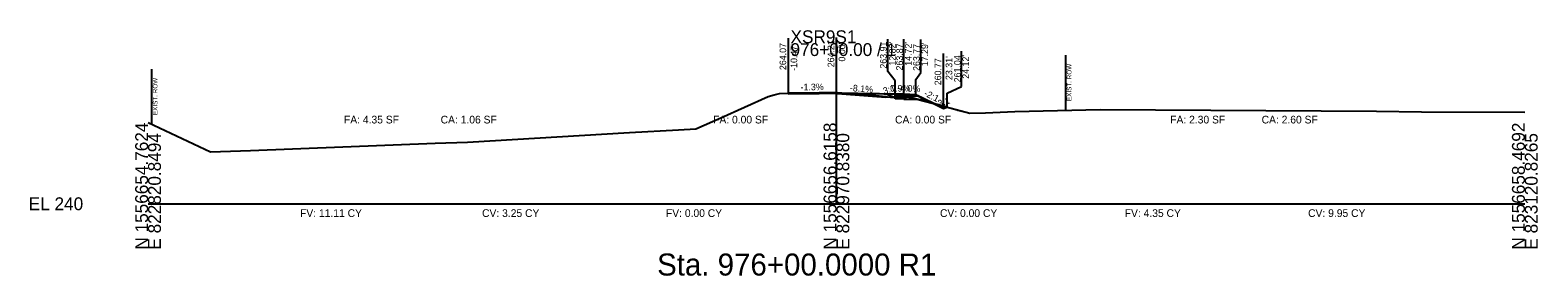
# Model space of a CAD drawing. Extents: x -26 to 823017, y -16 to 1558356.
# Drawn here: x 1974.3 to 2302.8, y 7484.3 to 7537.8 of the extents above; entities that cross this region are included whole.
import ezdxf

# ---------------------------------------------------------------- set-up
doc = ezdxf.new("R2010")
doc.units = 0
for name, color, linetype in [('ASPHALT_19MM1', 7, 'Continuous'), ('CONST_DCH', 7, 'Continuous'), ('CONST_LV3', 7, 'Continuous'), ('Draft_XS_Grid', 7, 'Continuous'), ('Draft_XS_Text', 7, 'Continuous'), ('DTM_CORRIDOR', 7, 'Continuous'), ('DTM_P_FINISHED_GRADE2', 7, 'Continuous'), ('DTM_X_GROUND', 7, 'Continuous'), ('SLOPE_STAKES_FILL', 7, 'Continuous'), ('X_TRANS_EOP', 7, 'Continuous'), ('XS_CELL', 7, 'Continuous'), ('XS_P_ASPHALT', 7, 'Continuous'), ('XS_P_DR_GRAVEL', 7, 'Continuous'), ('XS_P_GROUND', 7, 'Continuous'), ('XS_P_NULL_POINT', 7, 'Continuous'), ('XS_P_SHOULDER', 7, 'Continuous'), ('XS_P_SUBGRADE_GRANULAR', 7, 'Continuous'), ('XS_P_SUBGRADE_LEVELING', 7, 'Continuous'), ('XS_P_SUBGRADE_MILLING', 7, 'Continuous'), ('XS_P_SUBGRADE_UNDERCUT', 7, 'Continuous'), ('XS_P_TX_CLEARZONE', 7, 'Continuous'), ('XS_P_TX_FS_BS', 7, 'Continuous'), ('XS_SHEET_EW_TX_AREA', 7, 'Continuous'), ('XS_SHEET_EW_TX_VOLUME', 7, 'Continuous'), ('XS_X_ROW', 7, 'Continuous')]:
    doc.layers.add(name, color=color, linetype=linetype)

msp = doc.modelspace()

# ---------------------------------------------------------------- linework, layer by layer
at = {"layer": 'ASPHALT_19MM1'}
msp.add_lwpolyline([(2162.82, 7523.75), (2162.82, 7523.54), (2164.72, 7523.5), (2164.72, 7523.7), (2162.82, 7523.75)], dxfattribs=at)
at = {"layer": 'CONST_LV3'}
for points in [[(2000, 7517.72), (2013.59, 7511.28), (2022.29, 7511.63), (2062.59, 7513.21), (2069.61, 7513.42), (2104.93, 7515.51), (2115.58, 7516.11), (2119.34, 7516.33), (2124.8, 7518.75), (2135.15, 7523.36), (2136.41, 7523.72), (2137.57, 7524.05), (2139.53, 7524.07), (2139.53, 7524.07)], [(2150, 7524.21), (2164, 7523.93)], [(2160.77, 7523.33), (2160.77, 7523.33), (2162.82, 7523.16), (2163.01, 7523.16), (2164.72, 7523.12), (2166.98, 7523.69), (2167.29, 7523.77), (2170.58, 7522.13), (2171.2, 7521.82), (2173.88, 7521.1), (2176.33, 7520.45), (2176.43, 7520.42), (2179.05, 7519.73), (2182.47, 7519.85), (2188.84, 7520.08), (2207.48, 7520.58), (2267.71, 7520.15), (2277.51, 7520.07), (2300, 7519.96)], [(2162.77, 7523.98), (2164, 7523.93), (2164, 7523.93)]]:
    msp.add_lwpolyline(points, dxfattribs=at)
at = {"layer": 'DTM_P_FINISHED_GRADE2'}
msp.add_lwpolyline([(2139.53, 7524.07), (2150, 7524.21), (2160.77, 7523.96)], dxfattribs=at)
at = {"layer": 'DTM_X_GROUND'}
for points in [[(2000, 7517.72), (2013.59, 7511.28), (2022.29, 7511.63), (2062.59, 7513.21), (2069.61, 7513.42), (2104.93, 7515.51), (2115.58, 7516.11), (2119.34, 7516.33), (2124.8, 7518.75), (2135.15, 7523.36), (2136.41, 7523.72), (2137.57, 7524.05), (2146.22, 7524.16), (2150.21, 7524.21), (2157.84, 7524.03), (2162.82, 7523.91), (2163.3, 7523.82), (2164.74, 7523.55), (2173.88, 7521.09), (2179.05, 7519.73), (2182.47, 7519.85), (2188.84, 7520.08), (2207.48, 7520.58), (2267.71, 7520.15), (2277.51, 7520.07), (2300, 7519.96)], [(2000, 7517.72), (2013.59, 7511.28), (2022.29, 7511.63), (2062.59, 7513.21), (2069.61, 7513.42), (2104.93, 7515.51), (2115.58, 7516.11), (2119.34, 7516.33), (2124.8, 7518.75), (2135.15, 7523.36), (2136.41, 7523.72), (2137.57, 7524.05), (2146.22, 7524.16), (2150.21, 7524.21), (2157.84, 7523.58), (2162.82, 7523.16), (2163.01, 7523.16), (2164.72, 7523.12), (2166.98, 7523.69), (2167.29, 7523.77), (2170.58, 7522.13), (2171.2, 7521.82), (2173.88, 7521.1), (2176.33, 7520.45), (2176.43, 7520.42), (2179.05, 7519.73), (2182.47, 7519.85), (2188.84, 7520.08), (2207.48, 7520.58), (2267.71, 7520.15), (2277.51, 7520.07), (2300, 7519.96)], [(2000, 7517.72), (2013.59, 7511.28), (2022.29, 7511.63), (2062.59, 7513.21), (2069.61, 7513.42), (2104.93, 7515.51), (2115.58, 7516.11), (2119.34, 7516.33), (2124.8, 7518.75), (2135.15, 7523.36), (2136.41, 7523.72), (2137.57, 7524.05), (2139.53, 7524.07), (2139.53, 7524.07), (2150, 7524.21), (2150, 7524.21), (2150, 7524.21), (2150, 7524.21), (2150, 7524.21), (2150, 7524.21), (2150, 7524.21), (2150, 7524.21), (2160.77, 7523.96), (2160.77, 7523.96), (2160.77, 7523.96), (2162.82, 7523.16), (2163.01, 7523.16), (2164.72, 7523.12), (2166.98, 7523.69), (2167.29, 7523.77), (2170.58, 7522.13), (2171.2, 7521.82), (2173.88, 7521.1), (2176.33, 7520.45), (2176.43, 7520.42), (2179.05, 7519.73), (2182.47, 7519.85), (2188.84, 7520.08), (2207.48, 7520.58), (2267.71, 7520.15), (2277.51, 7520.07), (2300, 7519.96)]]:
    msp.add_lwpolyline(points, dxfattribs=at)
at = {"layer": 'X_TRANS_EOP'}
msp.add_lwpolyline([(2162.82, 7523.91), (2162.82, 7523.75), (2164.72, 7523.7), (2164.72, 7523.87), (2162.82, 7523.91)], dxfattribs=at)
at = {"layer": 'XS_CELL'}
for p, q in [((2150, 7500), (2150, 7535)), ((2000, 7500), (2150, 7500)), ((2150, 7500), (2300, 7500))]:
    msp.add_line(p, q, dxfattribs=at)
at = {"layer": 'XS_P_ASPHALT'}
msp.add_lwpolyline([(2139.53, 7524.07), (2150, 7524.21), (2150, 7524.21), (2160.77, 7523.33), (2160.77, 7523.33), (2160.77, 7523.21), (2160.77, 7523.21), (2150, 7524.08), (2150, 7524.08), (2139.53, 7523.95), (2139.53, 7524.07)], dxfattribs=at)
at = {"layer": 'XS_P_DR_GRAVEL'}
msp.add_lwpolyline([(2164.72, 7523.87), (2164.72, 7523.5), (2167.99, 7523.42), (2167.29, 7523.77), (2164.72, 7523.87)], dxfattribs=at)
at = {"layer": 'XS_P_GROUND'}
for points in [[(2163.13, 7523.86), (2163.13, 7523.86), (2162.77, 7523.98)], [(2174.12, 7521.03), (2173.88, 7521.09), (2173.88, 7521.09), (2164.74, 7523.55), (2164.74, 7523.55), (2164.74, 7523.55), (2163.3, 7523.82), (2163.3, 7523.82), (2163.13, 7523.86)], [(2163.13, 7523.86), (2163.3, 7523.82), (2163.3, 7523.82), (2164.74, 7523.55), (2164.74, 7523.55), (2164.74, 7523.55), (2173.88, 7521.09), (2173.88, 7521.09), (2174.12, 7521.03)], [(2167.29, 7523.77), (2173.31, 7520.77), (2174.12, 7521.04)]]:
    msp.add_lwpolyline(points, dxfattribs=at)
at = {"layer": 'XS_P_SHOULDER'}
msp.add_lwpolyline([(2164.72, 7523.87), (2167.29, 7523.77)], dxfattribs=at)
at = {"layer": 'XS_P_SUBGRADE_GRANULAR'}
for points in [[(2162.82, 7522.87), (2162.82, 7523.91)], [(2164.72, 7522.83), (2163.01, 7522.87), (2162.82, 7522.87)], [(2164.72, 7522.83), (2166.72, 7522.78), (2169.39, 7522.72)]]:
    msp.add_lwpolyline(points, dxfattribs=at)
at = {"layer": 'XS_P_SUBGRADE_LEVELING'}
for points in [[(2160.77, 7523.21), (2157.84, 7523.45), (2157.84, 7523.45), (2150.21, 7524.06), (2150.21, 7524.06), (2150.21, 7524.06), (2150, 7524.08), (2146.22, 7524.03), (2146.22, 7524.03), (2139.53, 7523.95)], [(2139.53, 7523.95), (2146.22, 7524.03), (2146.22, 7524.03), (2150, 7524.08), (2150.21, 7524.06), (2150.21, 7524.06), (2150.21, 7524.06), (2157.84, 7523.45), (2157.84, 7523.45), (2160.77, 7523.21)]]:
    msp.add_lwpolyline(points, dxfattribs=at)
at = {"layer": 'XS_P_SUBGRADE_MILLING'}
msp.add_lwpolyline([(2157.84, 7523.58), (2150.21, 7524.21), (2150.21, 7524.21), (2150.21, 7524.21), (2150, 7524.21), (2146.22, 7524.16), (2146.22, 7524.16), (2139.53, 7524.07), (2139.53, 7523.95), (2146.22, 7524.03), (2146.22, 7524.03), (2150, 7524.08), (2150.21, 7524.06), (2150.21, 7524.06), (2150.21, 7524.06), (2157.84, 7523.45), (2157.84, 7523.45), (2160.77, 7523.21), (2160.77, 7523.33), (2157.84, 7523.58), (2157.84, 7523.58)], dxfattribs=at)
at = {"layer": 'XS_P_SUBGRADE_UNDERCUT'}
msp.add_lwpolyline([(2162.82, 7523.91), (2164.74, 7523.55), (2171.2, 7521.82), (2167.29, 7523.77)], close=True, dxfattribs=at)
at = {"layer": 'XS_P_TX_CLEARZONE'}
for p, q in [((2139.53, 7524.07), (2139.53, 7536.07)), ((2150, 7524.21), (2150, 7536.21)), ((2161.18, 7528.81), (2161.18, 7535.91)), ((2164.72, 7523.87), (2164.72, 7535.87)), ((2168.38, 7528.63), (2168.38, 7535.77)), ((2173.31, 7520.77), (2173.31, 7532.77)), ((2177.28, 7525.59), (2177.28, 7533.23)), ((2162.82, 7526.78), (2161.18, 7528.81)), ((2162.82, 7523.91), (2162.82, 7526.78)), ((2167.29, 7527.11), (2168.38, 7528.63)), ((2167.29, 7523.77), (2167.29, 7527.11)), ((2174.12, 7524.09), (2177.28, 7525.59)), ((2174.12, 7521.04), (2174.12, 7524.09))]:
    msp.add_line(p, q, dxfattribs=at)
at = {"layer": 'XS_X_ROW'}
for p, q in [((2200, 7520.38), (2200, 7532.38)), ((2000.84, 7517.32), (2000.84, 7529.32))]:
    msp.add_line(p, q, dxfattribs=at)

# ---------------------------------------------------------------- texts
at = {"layer": 'CONST_DCH'}
for p in [(2139.45, 7523.95), (2149.92, 7524.09), (2160.69, 7523.21)]:
    msp.add_text('X', height=0.24, dxfattribs=at).set_placement(p)
at = {"layer": 'CONST_LV3'}
for p in [(2162.69, 7523.86), (2163.05, 7523.74), (2174.04, 7520.92)]:
    msp.add_text('X', height=0.24, dxfattribs=at).set_placement(p)
at = {"layer": 'Draft_XS_Grid'}
msp.add_text('-', height=0.0001, dxfattribs=at).set_placement((2000, 7500))
at = {"layer": 'Draft_XS_Text'}
msp.add_text('Sta. 976+00.0000 R1', height=4.8, dxfattribs=at).set_placement((2110.92, 7484.35))
at = {"layer": 'DTM_CORRIDOR'}
for p in [(2162.74, 7523.79), (2164.64, 7523.75)]:
    msp.add_text('X', height=0.24, dxfattribs=at).set_placement(p)
at = {"layer": 'SLOPE_STAKES_FILL'}
msp.add_text('X', height=0.24, dxfattribs=at).set_placement((2173.23, 7520.65))
at = {"layer": 'XS_CELL'}
for s, p in [('XSR9S1', (2140, 7535)), ('976+00.00 / 1', (2140, 7532.2)), ('EL 240', (1974, 7498.6))]:
    msp.add_text(s, height=2.8, dxfattribs=at).set_placement(p)
for s, p in [('N 1556654.7624', (2000, 7490)), ('N 1556656.6158', (2150, 7490)), ('N 1556658.4692', (2300, 7490)), ('E 822820.8494', (2002.8, 7490)), ('E 822970.8380', (2152.8, 7490)), ('E 823120.8265', (2302.8, 7490))]:
    msp.add_text(s, height=2.8, rotation=90, dxfattribs=at).set_placement(p)
at = {"layer": 'XS_P_NULL_POINT'}
msp.add_text('X', height=0.24, dxfattribs=at).set_placement((2174.04, 7520.92))
at = {"layer": 'XS_P_SHOULDER'}
msp.add_text('X', height=0.24, dxfattribs=at).set_placement((2167.21, 7523.65))
at = {"layer": 'XS_P_TX_CLEARZONE'}
for s, p in [('264.07', (2139.05, 7529.14)), ("-10.47'", (2141.45, 7528.98)), ('264.21', (2149.52, 7529.75)), ("0.00'", (2151.92, 7530.99)), ('263.91', (2160.94, 7529.45)), ("12.82'", (2162.91, 7530.11)), ('263.87', (2164.47, 7529.05)), ("14.72'", (2166.38, 7530.07)), ('263.77', (2168.16, 7528.95)), ("17.29'", (2169.97, 7529.97)), ('260.77', (2172.83, 7525.83)), ("23.31'", (2175.23, 7526.97)), ('261.04', (2177.08, 7526.47)), ("24.12'", (2178.88, 7527.24))]:
    msp.add_text(s, height=1.44, rotation=90, dxfattribs=at).set_placement(p)
at = {"layer": 'XS_P_TX_FS_BS'}
for s, rotation, p in [('-1.3%', 0.7295, (2142.2, 7524.71)), ('-8.1%', 355.3727, (2152.89, 7524.57)), ('3:1', 17.7719, (2160.42, 7523.85)), ('0.9%', 0.5228, (2161.71, 7524.44)), ('-4.0%', 357.7106, (2163.24, 7524.53)), ('-2:1', 333.4814, (2168.94, 7523.62)), ('3:1', 18.3928, (2172.36, 7521.09))]:
    msp.add_text(s, height=1.44, rotation=rotation, dxfattribs=at).set_placement(p)
at = {"layer": 'XS_SHEET_EW_TX_AREA'}
for s, p in [('FA: 4.35 SF', (2042.69, 7517.5)), ('CA: 1.06 SF', (2063.75, 7517.5)), ('FA: 0.00 SF', (2123.13, 7517.5)), ('CA: 0.00 SF', (2162.77, 7517.5)), ('FA: 2.30 SF', (2222.73, 7517.5)), ('CA: 2.60 SF', (2242.65, 7517.5))]:
    msp.add_text(s, height=1.68, dxfattribs=at).set_placement(p)
at = {"layer": 'XS_SHEET_EW_TX_VOLUME'}
for s, p in [('FV: 11.11 CY', (2033.12, 7497.12)), ('CV: 3.25 CY', (2072.78, 7497.12)), ('FV: 0.00 CY', (2112.85, 7497.12)), ('CV: 0.00 CY', (2172.56, 7497.12)), ('FV: 4.35 CY', (2212.82, 7497.12)), ('CV: 9.95 CY', (2252.78, 7497.12))]:
    msp.add_text(s, height=1.68, dxfattribs=at).set_placement(p)
at = {"layer": 'XS_X_ROW'}
for p in [(2201.2, 7522.38), (2002.04, 7519.32)]:
    msp.add_text('EXIST. ROW', height=1, rotation=90, dxfattribs=at).set_placement(p)

doc.saveas('drawing.dxf')
